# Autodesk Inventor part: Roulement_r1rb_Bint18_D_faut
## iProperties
Created: 2011-10
Part Number: Roulement_r1rb_Bint18_D_faut
Document SubType Name: Modeling
Designer: Bruno
Author: Bruno
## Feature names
1. Base1
